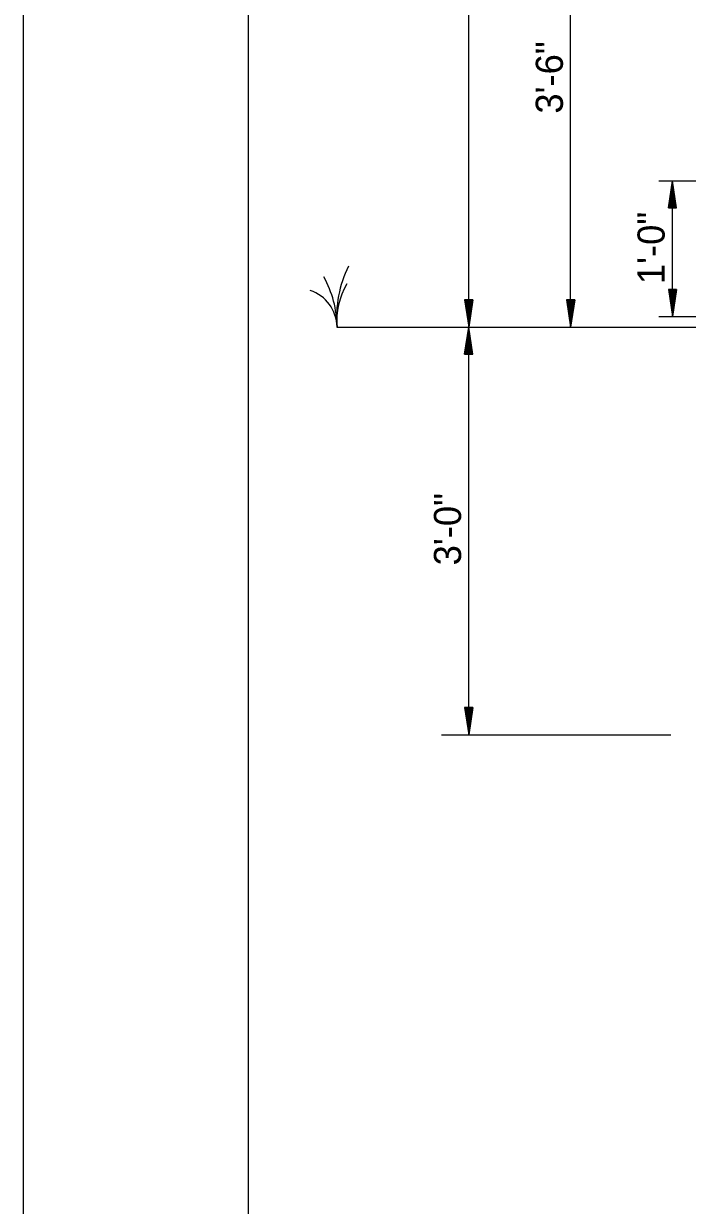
# Model space of a CAD drawing. Extents: x 1370050 to 1370716, y 380076 to 380502.
# Drawn here: x 1370049.7 to 1370122.9, y 380290.6 to 380421.1 of the extents above; entities that cross this region are included whole.
import ezdxf

# ---------------------------------------------------------------- set-up
doc = ezdxf.new("R2010")
doc.units = 0
for name, color, linetype in [('R_Border', 7, 'Continuous'), ('R_Grid', 7, 'Continuous'), ('R_No Plot', 7, 'Continuous')]:
    doc.layers.add(name, color=color, linetype=linetype)

msp = doc.modelspace()

# ---------------------------------------------------------------- linework, layer by layer
at = {"layer": 'R_Border'}
msp.add_line((1370074.49, 380083.66), (1370074.49, 380494.58), dxfattribs=at)
at = {"layer": 'R_Grid'}
for p, q in [((1370098.79, 380387.58), (1370098.79, 380479.98)), ((1370110.04, 380387.58), (1370110.04, 380440.08)), ((1370119.79, 380403.73), (1370128.53, 380403.73)), ((1370120.84, 380400.73), (1370121.29, 380403.73)), ((1370121.29, 380388.73), (1370121.29, 380403.73)), ((1370121.74, 380400.73), (1370121.29, 380403.73)), ((1370120.92, 380400.73), (1370121.29, 380403.22)), ((1370121, 380400.73), (1370121.29, 380402.71)), ((1370121.07, 380400.73), (1370121.29, 380402.21)), ((1370121.67, 380400.73), (1370121.29, 380403.22)), ((1370121.59, 380400.73), (1370121.29, 380402.71)), ((1370121.52, 380400.73), (1370121.29, 380402.21)), ((1370121.15, 380400.73), (1370121.29, 380401.7)), ((1370121.22, 380400.73), (1370121.29, 380401.2)), ((1370121.44, 380400.73), (1370121.29, 380401.7)), ((1370121.36, 380400.73), (1370121.29, 380401.2)), ((1370120.84, 380400.73), (1370121.74, 380400.73)), ((1370120.84, 380391.73), (1370121.29, 380388.73)), ((1370121.74, 380391.73), (1370120.84, 380391.73)), ((1370120.92, 380391.73), (1370121.29, 380389.23)), ((1370121, 380391.73), (1370121.29, 380389.74)), ((1370121.07, 380391.73), (1370121.29, 380390.24)), ((1370121.15, 380391.73), (1370121.29, 380390.75)), ((1370121.22, 380391.73), (1370121.29, 380391.25)), ((1370121.74, 380391.73), (1370121.29, 380388.73)), ((1370121.44, 380391.73), (1370121.29, 380390.75)), ((1370121.59, 380391.73), (1370121.29, 380389.74)), ((1370121.67, 380391.73), (1370121.29, 380389.23)), ((1370121.52, 380391.73), (1370121.29, 380390.24)), ((1370121.36, 380391.73), (1370121.29, 380391.25)), ((1370098.34, 380390.58), (1370098.79, 380387.58)), ((1370099.24, 380390.58), (1370098.34, 380390.58)), ((1370098.42, 380390.58), (1370098.79, 380388.08)), ((1370098.5, 380390.58), (1370098.79, 380388.59)), ((1370098.57, 380390.58), (1370098.79, 380389.09)), ((1370098.65, 380390.58), (1370098.79, 380389.6)), ((1370098.72, 380390.58), (1370098.79, 380390.1)), ((1370099.24, 380390.58), (1370098.79, 380387.58)), ((1370098.94, 380390.58), (1370098.79, 380389.6)), ((1370099.09, 380390.58), (1370098.79, 380388.59)), ((1370099.17, 380390.58), (1370098.79, 380388.08)), ((1370099.02, 380390.58), (1370098.79, 380389.09)), ((1370098.86, 380390.58), (1370098.79, 380390.1)), ((1370109.59, 380390.58), (1370110.04, 380387.58)), ((1370110.49, 380390.58), (1370109.59, 380390.58)), ((1370109.67, 380390.58), (1370110.04, 380388.08)), ((1370109.75, 380390.58), (1370110.04, 380388.59)), ((1370109.82, 380390.58), (1370110.04, 380389.09)), ((1370109.9, 380390.58), (1370110.04, 380389.6)), ((1370109.97, 380390.58), (1370110.04, 380390.1)), ((1370110.49, 380390.58), (1370110.04, 380387.58)), ((1370110.19, 380390.58), (1370110.04, 380389.6)), ((1370110.34, 380390.58), (1370110.04, 380388.59)), ((1370110.42, 380390.58), (1370110.04, 380388.08)), ((1370110.27, 380390.58), (1370110.04, 380389.09)), ((1370110.11, 380390.58), (1370110.04, 380390.1)), ((1370119.79, 380388.73), (1370128.53, 380388.73)), ((1370084.25, 380387.58), (1370242.79, 380387.58)), ((1370098.34, 380384.58), (1370098.79, 380387.58)), ((1370098.42, 380384.58), (1370098.79, 380387.08)), ((1370098.5, 380384.58), (1370098.79, 380386.56)), ((1370098.79, 380342.58), (1370098.79, 380387.58)), ((1370099.24, 380384.58), (1370098.79, 380387.58)), ((1370099.17, 380384.58), (1370098.79, 380387.08)), ((1370099.09, 380384.58), (1370098.79, 380386.56)), ((1370098.57, 380384.58), (1370098.79, 380386.06)), ((1370098.65, 380384.58), (1370098.79, 380385.55)), ((1370099.02, 380384.58), (1370098.79, 380386.06)), ((1370098.94, 380384.58), (1370098.79, 380385.55)), ((1370098.34, 380384.58), (1370099.24, 380384.58)), ((1370098.72, 380384.58), (1370098.79, 380385.05)), ((1370098.86, 380384.58), (1370098.79, 380385.05)), ((1370098.34, 380345.58), (1370098.79, 380342.58)), ((1370099.24, 380345.58), (1370098.34, 380345.58)), ((1370098.42, 380345.58), (1370098.79, 380343.08)), ((1370098.5, 380345.58), (1370098.79, 380343.59)), ((1370098.57, 380345.58), (1370098.79, 380344.09)), ((1370098.65, 380345.58), (1370098.79, 380344.6)), ((1370098.72, 380345.58), (1370098.79, 380345.1)), ((1370099.24, 380345.58), (1370098.79, 380342.58)), ((1370098.94, 380345.58), (1370098.79, 380344.6)), ((1370099.09, 380345.58), (1370098.79, 380343.59)), ((1370099.17, 380345.58), (1370098.79, 380343.08)), ((1370099.02, 380345.58), (1370098.79, 380344.09)), ((1370098.86, 380345.58), (1370098.79, 380345.1)), ((1370095.79, 380342.58), (1370121.11, 380342.58))]:
    msp.add_line(p, q, dxfattribs=at)
for centre, radius, start, end in [((1370096.84, 380388.68), 12.63, 153.6036, 185.017), ((1370072.78, 380387.5), 11.48, 0.407, 29.2294), ((1370092.21, 380388.23), 7.99, 149.1449, 184.6717), ((1370079.91, 380387.5), 4.35, 1.0116, 71.214)]:
    msp.add_arc(centre, radius, start, end, dxfattribs=at)
at = {"layer": 'R_No Plot'}
msp.add_lwpolyline([(1370049.67, 380502.37), (1370716.35, 380502.37), (1370716.35, 380075.69), (1370049.67, 380075.69)], close=True, dxfattribs=at)

# ---------------------------------------------------------------- texts
at = {"layer": 'R_Grid'}
for s, p in [('3\'-6"', (1370109.19, 380411.13)), ('1\'-0"', (1370120.42, 380392.31)), ('3\'-0"', (1370097.95, 380361.27))]:
    msp.add_text(s, height=3, rotation=90, dxfattribs=at).set_placement(p)

doc.saveas('drawing.dxf')
